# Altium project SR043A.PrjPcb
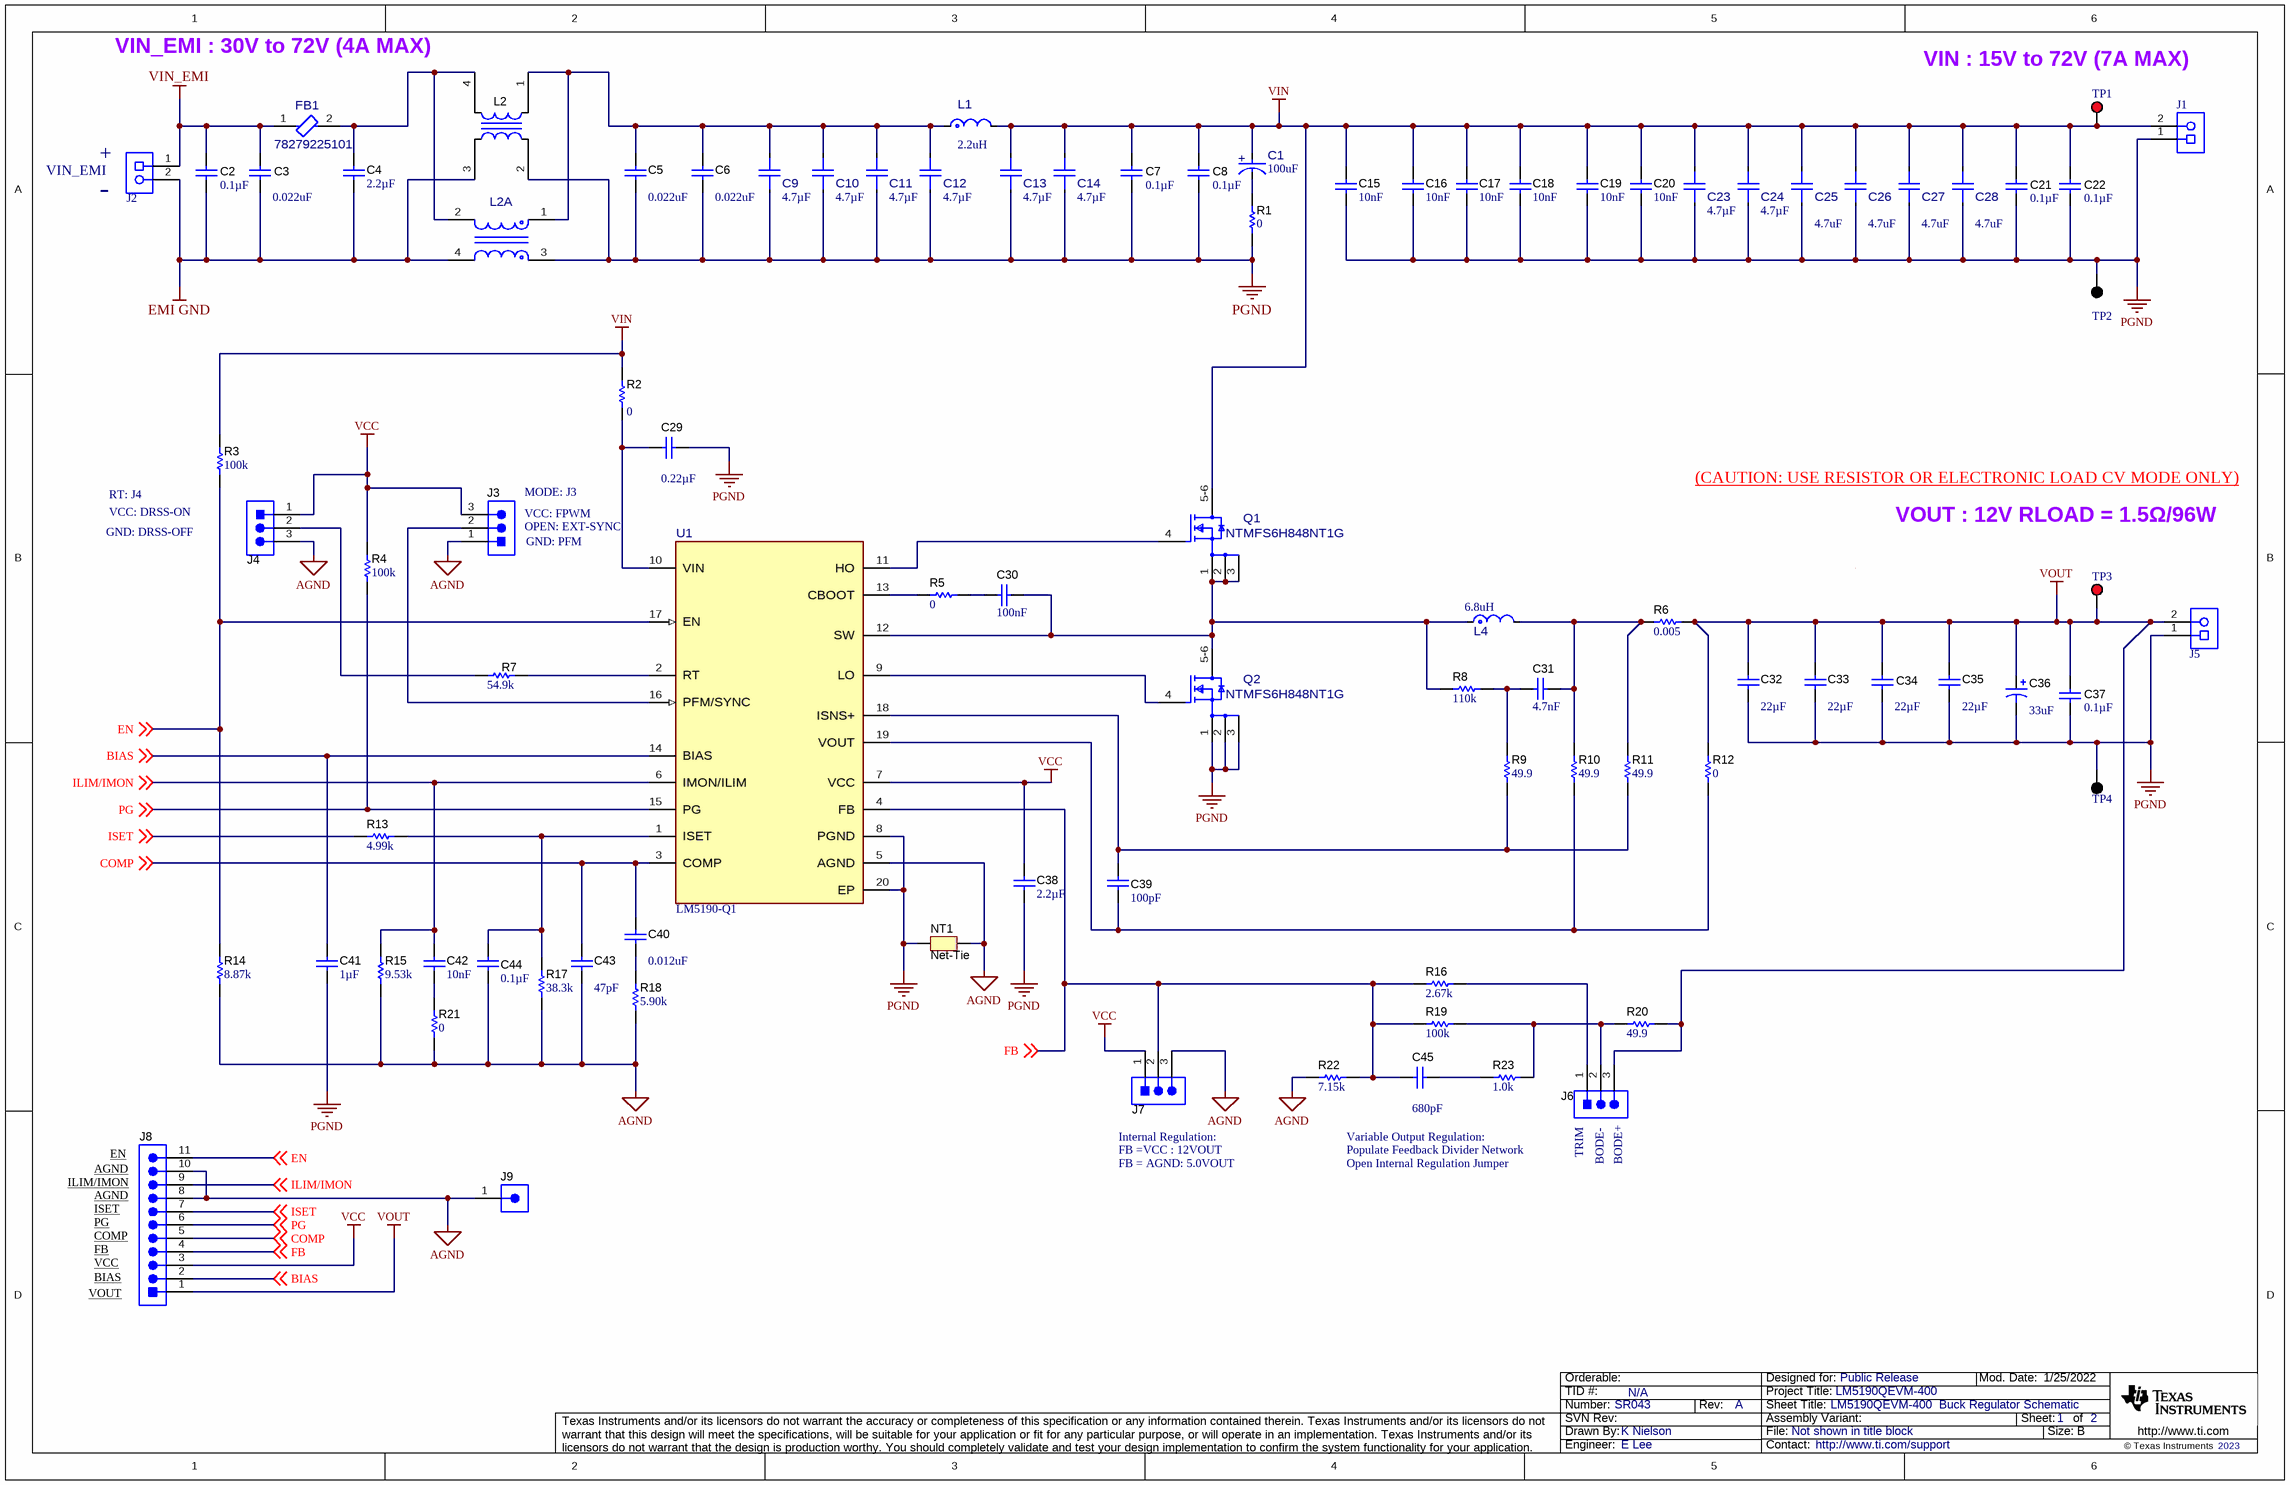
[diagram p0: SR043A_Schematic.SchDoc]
CopyrightYear: 2023; PCB_Layout: K Nielson; PCB_Rev: A; PRJ_Customer: Public Release; PRJ_Engineer: E Lee; PRJ_Number: SR043; PRJ_Title: LM5190QEVM-400; SCH_Rev: A; TechSupport: http://www.ti.com/support; TID: N/A
2 sheets, 121 parts. Net scope: global (net labels, ports and power ports of the same name join across sheets).
Board file: SR043A.PcbDoc
Sheets:
  SR043A_Schematic.SchDoc
  SR043A_Hardware.SchDoc

## Sheet SR043A_Schematic.SchDoc: LM5190QEVM-400  Buck Regulator Schematic
size 431 x 279 mm; Date: Not shown in title block; ApprovedBy: Not shown in title block; CheckedBy: Not shown in title block; Author: Not shown in title block; CompanyName: Not shown in title block; DrawnBy: K Nielson; Engineer: Not shown in title block; Organization: Not shown in title block; Address1: Not shown in title block; Address2: Not shown in title block; Address3: Not shown in title block; Address4: Not shown in title block; DocumentNumber: 1; Revision: Use project parameter SCH_Rev; SheetNumber: 1; SheetTotal: 2; PageSetup: Record=PageOptions¦CenterHorizontal=True¦CenterVertical=True¦PrintScale=1.00¦XCorrection=1.00¦YCorrection=1.00¦PrintKind=0¦BorderSize=5000000¦LeftOffset=0¦BottomOffset=0¦Orientation=2¦PaperLength=1000¦PaperWidth=1000¦Scale=100¦PaperSource=15¦PrintQuality=600¦MediaType=1¦DitherType=10¦PaperKind=Letter¦PrintScaleMode=1

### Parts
C1  ValueDisplayed: 100uF  [FP-EMVY101ARA101MKE0S_RADIAL-MFG]  (hidden comment: EMVY101ARA101MKE0S)
C2  ValueDisplayed: 0.1µF  [0603L]  (hidden comment: HMK107B7104MAHT)
C3  ValueDisplayed: 0.022uF  [0603L]  (hidden comment: CGA3E2X7R2A223K080AA)
C4  Cap_F: 2.2µF  [1206_190]  (hidden comment: CGA5L3X7S2A225M160AB)
C5  ValueDisplayed: 0.022uF  [0603L]  (hidden comment: CGA3E2X7R2A223K080AA)
C6  ValueDisplayed: 0.022uF  [0603L]  (hidden comment: CGA3E2X7R2A223K080AA)
C7  ValueDisplayed: 0.1µF  [0603L]  (hidden comment: HMK107B7104MAHT)
C8  ValueDisplayed: 0.1µF  [0603L]  (hidden comment: HMK107B7104MAHT)
C9  Cap_F: 4.7µF  [FP-CNC6P1X7R2A475K250AE_1210-MFG]  (hidden comment: CNC6P1X7R2A475K250AE)
C10  Cap_F: 4.7µF  [FP-CNC6P1X7R2A475K250AE_1210-MFG]  (hidden comment: CNC6P1X7R2A475K250AE)
C11  Cap_F: 4.7µF  [FP-CNC6P1X7R2A475K250AE_1210-MFG]  (hidden comment: CNC6P1X7R2A475K250AE)
C12  Cap_F: 4.7µF  [FP-CNC6P1X7R2A475K250AE_1210-MFG]  (hidden comment: CNC6P1X7R2A475K250AE)
C13  Cap_F: 4.7µF  [FP-CNC6P1X7R2A475K250AE_1210-MFG]  (hidden comment: CNC6P1X7R2A475K250AE)
C14  Cap_F: 4.7µF  [FP-CNC6P1X7R2A475K250AE_1210-MFG]  (hidden comment: CNC6P1X7R2A475K250AE)
C15  Cap_F: 10nF  [0603L]  (hidden comment: 885012206114)
C16  Cap_F: 10nF  [0603L]  (hidden comment: 885012206114)
C17  Cap_F: 10nF  [0603L]  (hidden comment: 885012206114)
C18  Cap_F: 10nF  [0603L]  (hidden comment: 885012206114)
C19  Cap_F: 10nF  [0603L]  (hidden comment: 885012206114)
C20  Cap_F: 10nF  [0603L]  (hidden comment: 885012206114)
C21  ValueDisplayed: 0.1µF  [0603L]  (hidden comment: HMK107B7104MAHT)
C22  ValueDisplayed: 0.1µF  [0603L]  (hidden comment: HMK107B7104MAHT)
C23  Cap_F: 4.7µF  [FP-CNC6P1X7R2A475K250AE_1210-MFG]  (hidden comment: CNC6P1X7R2A475K250AE)
C24  Cap_F: 4.7µF  [FP-CNC6P1X7R2A475K250AE_1210-MFG]  (hidden comment: CNC6P1X7R2A475K250AE)
C25  ValueDisplayed: 4.7uF  [FP-CNC6P1X7R2A475K250AE_1210-MFG]  (hidden comment: CNC6P1X7R2A475K250AE)
C26  ValueDisplayed: 4.7uF  [FP-CNC6P1X7R2A475K250AE_1210-MFG]  (hidden comment: CNC6P1X7R2A475K250AE)
C27  ValueDisplayed: 4.7uF  [FP-CNC6P1X7R2A475K250AE_1210-MFG]  (hidden comment: CNC6P1X7R2A475K250AE)
C28  ValueDisplayed: 4.7uF  [FP-CNC6P1X7R2A475K250AE_1210-MFG]  (hidden comment: CNC6P1X7R2A475K250AE)
C29  ValueDisplayed: 0.22µF  [0603L]  (hidden comment: HMK107C7224MAHTE)
C30  Cap_F: 100nF  [0603L]  (hidden comment: HMK107B7104MAHT)
C31  Cap_F: 4.7nF  [0603L]  (hidden comment: GCM188R72A472KA37D)
C32  ValueDisplayed: 22µF  [1210_280]  (hidden comment: C1210C226K3RAC7800)
C33  ValueDisplayed: 22µF  [1210_280]  (hidden comment: C1210C226K3RAC7800)
C34  ValueDisplayed: 22µF  [1210_280]  (hidden comment: C1210C226K3RAC7800)
C35  ValueDisplayed: 22µF  [1210_280]  (hidden comment: C1210C226K3RAC7800)
C36  ValueDisplayed: 33uF  [CAPSMT_62_F60]  (hidden comment: EMVH250ADA330MF60G)
C37  ValueDisplayed: 0.1µF  [0603L]  (hidden comment: HMK107B7104MAHT)
C38  Cap_F: 2.2µF  [0603L]  (hidden comment: CGA3E1X7S1C225M080AC)
C39  ValueDisplayed: 100pF  [0603L]  (hidden comment: GRM1885C2A101JA01D)
C40  ValueDisplayed: 0.012uF  [0603L]  (hidden comment: C0603C123J3GACTU)
C41  Cap_F: 1µF  [0603L]  (hidden comment: 06033C105KAT2A)
C42  Cap_F: 10nF  [0603L]  (hidden comment: 885012206114)
C43  ValueDisplayed: 47pF  [0603L]  (hidden comment: CGA3E2NP01H470J080AA)
C44  ValueDisplayed: 0.1µF  [0603L]  (hidden comment: HMK107B7104MAHT)
C45  ValueDisplayed: 680pF  [0603L]  (hidden comment: GRM1885C1E681JA01D)
FB1  78279225101  [FP-78279225101_3312-MFG]
J1  691253510002  [FP-691253510002_CONN_TERM_BLOCK2-MFG]  (value not drawn)
J2  691253510002  [FP-691253510002_CONN_TERM_BLOCK2-MFG]  (value not drawn)
J3  61300311121  [WURTH_61300311121]  (value not drawn)
J4  61300311121  [WURTH_61300311121]  (value not drawn)
J5  691253510002  [FP-691253510002_CONN_TERM_BLOCK2-MFG]  (value not drawn)
J6  61300311121  [WURTH_61300311121]  (value not drawn)
J7  61300311121  [WURTH_61300311121]  (value not drawn)
J8  TSW-111-07-G-S  [TSW-111-07-G-S]  (value not drawn)
J9  1040  [CONN_1040]  (value not drawn)
L1  value 2.2uH  [FP-XGL4040-222MEC_SMT2_4MM0_4MM0-MFG]  (hidden comment: XGL4040-222MEC)
L2  ACM70V-701-2PL-TL00  [IND_TDK_ACM7060]  (value not drawn)
L2A  744237701  [FP-744237701_SMT_CHOKE_12MM00_11MM00-MFG]  (value not drawn)
L4  value 6.8uH  [FP-XGL1060-682MEC_SMT_IND_10MM0_11MM3-MFG]  (hidden comment: XGL1060-682MEC)
NT1  Net-Tie  [Net-Tie_10mil]  (net tie, no BOM)
Q1  NTMFS6H848NT1G  [FP-NTMFS6H848NT1G_DFN5-MFG]
Q2  NTMFS6H848NT1G  [FP-NTMFS6H848NT1G_DFN5-MFG]
R1  ValueDisplayed: 0  [1206]  (hidden comment: RCA12060000ZSEA)
R2  ValueDisplayed: 0  [0603L]  (hidden comment: RC0603JR-070RL)
R3  ValueDisplayed: 100k  [0603L]  (hidden comment: RC0603FR-07100KL)
R4  ValueDisplayed: 100k  [0603L]  (hidden comment: RC0603FR-07100KL)
R5  ValueDisplayed: 0  [0603L]  (hidden comment: RC0603JR-070RL)
R6  ValueDisplayed: 0.005  [2512_WIDE]  (hidden comment: FCSL64R005FER)
R7  ValueDisplayed: 54.9k  [0603L]  (hidden comment: RC0603FR-0754K9L)
R8  ValueDisplayed: 110k  [0603L]  (hidden comment: CRCW0603110KFKEA)
R9  ValueDisplayed: 49.9  [0603L]  (hidden comment: ERJ-3EKF49R9V)
R10  ValueDisplayed: 49.9  [0603L]  (hidden comment: ERJ-3EKF49R9V)
R11  ValueDisplayed: 49.9  [0603L]  (hidden comment: ERJ-3EKF49R9V)
R12  ValueDisplayed: 0  [0603L]  (hidden comment: RC0603JR-070RL)
R13  ValueDisplayed: 4.99k  [0603L]  (hidden comment: RC0603FR-074K99L)
R14  ValueDisplayed: 8.87k  [0603L]  (hidden comment: RC0603FR-078K87L)
R15  ValueDisplayed: 9.53k  [0603L]  (hidden comment: RC0603FR-079K53L)
R16  ValueDisplayed: 2.67k  [0603L]  (hidden comment: RC0603FR-072K67L)
R17  ValueDisplayed: 38.3k  [0603L]  (hidden comment: RC0603FR-0738K3L)
R18  ValueDisplayed: 5.90k  [0603L]  (hidden comment: RC0603FR-075K9L)
R19  ValueDisplayed: 100k  [0603L]  (hidden comment: RC0603FR-07100KL)
R20  ValueDisplayed: 49.9  [0603L]  (hidden comment: M55342K12B49D9T)
R21  ValueDisplayed: 0  [0603L]  (hidden comment: RC0603JR-070RL)
R22  ValueDisplayed: 7.15k  [0603L]  (hidden comment: RC0603FR-077K15L)
R23  ValueDisplayed: 1.0k  [0603L]  (hidden comment: RC0603JR-071KL)
TP1  5000  [Keystone5000]  (value not drawn)
TP2  5001  [Keystone5001]  (value not drawn)
TP3  5000  [Keystone5000]  (value not drawn)
TP4  5001  [Keystone5001]  (value not drawn)
U1  LM5190-Q1  [RGY0019B-MFG]

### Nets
AGND: C43.2 C44.1 J3.1 J4.3 J7.3 J8.8 J8.10 J9.1 NT1.2 R14.1 R15.1 R17.1 R18.1 R21.2 R22.1 U1.5(AGND)
EMI GND: C2.2 C3.2 C4.2 J2.2 L2.3 L2A.4
PGND: C5.2 C6.2 C7.2 C8.2 C9.1 C10.1 C11.1 C12.1 C13.1 C14.1 C15.2 C16.2 C17.2 C18.2 C19.2 C20.2 C21.2 C22.2 C23.1 C24.1 C25.1 C26.1 C27.1 C28.1 C29.1 C32.2 C33.2 C34.2 C35.2 C36.2(-) C37.2 C38.2 C41.2 J1.1 J5.1 L2.2 L2A.3 NT1.1 Q2.1(S) Q2.2(S) Q2.3(S) R1.2 TP2.1 TP4.1 U1.8(PGND) U1.20(EP)
VCC: C38.1 J3.3 J4.1 J7.1 J8.3 R4.2 U1.7(VCC)
VIN: C1.2(ANODE) C7.1 C8.1 C13.2 C14.2 C15.1 C16.1 C17.1 C18.1 C19.1 C20.1 C21.1 C22.1 C23.2 C24.2 C25.2 C26.2 C27.2 C28.2 J1.2 L1.2 Q1.5-6(D) R2.2 R3.2 TP1.1
VIN_EMI: C2.1 C3.1 FB1.1 J2.1
VOUT: C32.1 C33.1 C34.1 C35.1 C36.1(+) C37.1 J5.2 J6.3 J8.1 R6.2 R12.2 R20.2 TP3.1
BIAS: C41.1 J8.2 U1.14(BIAS) ; off-sheet BIAS
COMP: C40.1 C43.1 J8.5 U1.3(COMP) ; off-sheet COMP
EN: J8.11 R3.1 R14.2 U1.17(EN) ; off-sheet EN
FB: C45.2 J7.2 J8.4 R16.1 R19.1 R22.2 U1.4(FB) ; off-sheet FB
ILIM/IMON: C42.1 J8.9 R15.2 U1.6(IMON/ILIM) ; off-sheet ILIM/IMON
ISET: J8.7 R13.1 ; off-sheet ISET
PG: J8.6 R4.1 U1.15(PG) ; off-sheet PG
NetC1_1: C1.1(CATHODE) R1.1
NetC4_1: C4.1 FB1.2 L2.4 L2A.2
NetC5_1: C5.1 C6.1 C9.2 C10.2 C11.2 C12.2 L1.1 L2.1 L2A.1
NetC29_2: C29.2 R2.1 U1.10(VIN)
NetC30_1: C30.1 L4.1 Q1.1(S) Q1.2(S) Q1.3(S) Q2.5-6(D) R8.1 U1.12(SW)
NetC30_2: C30.2 R5.2
NetC31_1: C31.1 R8.2 R9.2
NetC31_2: C31.2 L4.2 R6.1 R10.2 R11.1
NetC39_1: C39.1 R10.1 R12.1 U1.19(VOUT)
NetC39_2: C39.2 R9.1 R11.2 U1.18(ISNS+)
NetC40_2: C40.2 R18.2
NetC42_2: C42.2 R21.1
NetC44_2: C44.2 R13.2 R17.2 U1.1(ISET)
NetC45_1: C45.1 R23.1
NetJ3_2: J3.2 U1.16(PFM/SYNC)
NetJ4_2: J4.2 R7.2
NetJ6_1: J6.1 R16.2
NetJ6_2: J6.2 R19.2 R20.1 R23.2
NetQ1_4: Q1.4(G) U1.11(HO)
NetQ2_4: Q2.4(G) U1.9(LO)
NetR5_1: R5.1 U1.13(CBOOT)
NetR7_1: R7.1 U1.2(RT)

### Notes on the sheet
- VIN_EMI : 30V to 72V (4A MAX)
- VIN : 15V to 72V (7A MAX)
- (near J2) +
- VIN_EMI
- (near J2) -
- RT: J4
- (near J3) MODE: J3
- (CAUTION: USE RESISTOR OR ELECTRONIC LOAD CV MODE ONLY) <aDD tEST pOINT>
- GND: DRSS-OFF
- (near R3) VCC: DRSS-ON
- (near J3) VCC: FPWM
- (near J3) OPEN: EXT-SYNC
- (near J3) GND: PFM
- VOUT : 12V RLOAD = 1.5Ω/96W
- (near J8) AGND <aDD tEST pOINT>
- (near J8) EN <aDD tEST pOINT>
- Internal Regulation:
- FB =VCC : 12VOUT
- FB = AGND: 5.0VOUT
- Variable Output Regulation:
- Populate Feedback Divider Network
- Open Internal Regulation Jumper
- (near J6) TRIM
- (near J6) BODE-
- (near J6) BODE+
- (near J8) ILIM/IMON <aDD tEST pOINT>
- (near J8) ISET <aDD tEST pOINT>
- PG <aDD tEST pOINT>
- (near J8) COMP <aDD tEST pOINT>
- VOUT <aDD tEST pOINT>
- (near J8) BIAS <aDD tEST pOINT>
- FB <aDD tEST pOINT>
- VCC <aDD tEST pOINT>

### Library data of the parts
C1 = CMP-0094051-1: 100uF 100V 20% Aluminum Electrolytic Capacitors Radial, Can - SMD - 5000 Hrs @ 105°C; Manufacturer: United Chemi-Con; Value: 100µF; IRMS_A: 450mA; Life: 5000Hours; SizeZ_mm: 14mm; AEC Grade: Grade 2; Leakage Current: 100uA; Dissipation Factor: 10%; AEC Qualified: Yes
C2 C7 C8 C21 C22 C37 = CMP-0078500-1: CAP, CERM, 0.1 µF,  VAC/100 VDC,+/- 20%, X7R, AEC-Q200 Grade 1, 0603; Manufacturer: Taiyo Yuden; TaMin_C: -55°C; Polarized: N; SizeAreaWB_mm2: 4.68; U/M: EA; Value: 0.1uF; TaMax_C: 125°C; SizeZ_mm: 1; SizeX_mm: 1.6; SizeY_mm: 0.8; Cap_Case: 0603; Value2: 100V; SizeArea_mm2: 1.28; AEC Qualified: Y; Cap_F: 100nF; AEC Category: Q200
C3 C5 C6 = CMP-0007086-4: CAP, CERM, 0.022 uF, 100 V, +/- 10%, X7R, AEC-Q200 Grade 1, 0603; Manufacturer: TDK; TaMin_C: -55°C; ESR_ohm: 83.542m; Polarized: N; SizeAreaWB_mm2: 4.68; Value1: 0.083542 ohm; U/M: EA; TaMax_C: 125°C; SizeZ_mm: 1; SizeX_mm: 1.6; SizeY_mm: 0.8; Cap_Case: 0603; Value2: 100V; SizeArea_mm2: 1.28; AEC Qualified: Y; Cap_F: 22nF; IRMS_A: 609.312mA; AEC Category: Q200
C4 = CMP-0008791-2: CAP, CERM, 2.2 uF, 100 V, +/- 20%, X7S, AEC-Q200 Grade 1, 1206_190; Manufacturer: TDK; TaMin_C: -55°C; Polarized: N; SizeAreaWB_mm2: 10.92; Value1: Unknown; U/M: EA; Value: 2.2uF; TaMax_C: 125°C; SizeZ_mm: 1.9; SizeX_mm: 3.2; SizeY_mm: 1.6; Cap_Case: 1206; Value2: 100V; SizeArea_mm2: 5.12; AEC Qualified: Y; AEC Grade: 1; AEC Category: Q200
C9-C14 C23 C24 = CMP-0094503-1: 4.7 µF ±10% 100V Ceramic Capacitor X7R 1210 (3225 Metric); Manufacturer: TDK; TempCo: 15%; Value: 4.7µF; SizeZ_mm: 2.8mm; AEC Qualified: No; ValueDisplayed: 4.7uF
C15-C20 C42 = CMP-0079993-1: CAP, CERM, 0.01 µF, 100 V,+/- 10%, X7R, 0603; Manufacturer: Wurth Elektronik; TaMin_C: -55°C; Polarized: N; SizeAreaWB_mm2: 4.68; U/M: EA; Value: 0.01uF; TaMax_C: 105°C; SizeZ_mm: 1; SizeX_mm: 1.6; SizeY_mm: 0.8; Cap_Case: 0603; Value2: 100V; SizeArea_mm2: 1.28; AEC Category: Q200; ValueDisplayed: 0.01µF
C25-C28 = CMP-0094503-1: 4.7 µF ±10% 100V Ceramic Capacitor X7R 1210 (3225 Metric); Manufacturer: TDK; TempCo: 15%; Value: 4.7µF; SizeZ_mm: 2.8mm; AEC Qualified: No
C29 = CMP-0077895-3: CAP, CERM, 0.22 µF, 100 V,+/- 20%, X7S, AEC-Q200 Grade 1, 0603; Manufacturer: Taiyo Yuden; TaMin_C: -55°C; Polarized: N; SizeAreaWB_mm2: 4.68; U/M: EA; Value: 0.22uF; TaMax_C: 125°C; SizeZ_mm: 1.0; SizeX_mm: 1.6; SizeY_mm: 0.8; Cap_Case: 0603; Value2: 100V; SizeArea_mm2: 1.28; AEC Qualified: Y; Cap_F: 220nF; AEC Grade: 1; AEC Category: Q200
C30 = CMP-0078500-1: CAP, CERM, 0.1 µF,  VAC/100 VDC,+/- 20%, X7R, AEC-Q200 Grade 1, 0603; Manufacturer: Taiyo Yuden; TaMin_C: -55°C; Polarized: N; SizeAreaWB_mm2: 4.68; U/M: EA; Value: 0.1uF; TaMax_C: 125°C; SizeZ_mm: 1; SizeX_mm: 1.6; SizeY_mm: 0.8; Cap_Case: 0603; Value2: 100V; SizeArea_mm2: 1.28; AEC Qualified: Y; AEC Category: Q200; ValueDisplayed: 0.1µF
C31 = CMP-0079247-1: CAP, CERM, 4700 pF, 100 V,+/- 10%, X7R, AEC-Q200 Grade 1, 0603; Manufacturer: MuRata; TaMin_C: -55°C; Polarized: N; SizeAreaWB_mm2: 4.68; U/M: EA; Value: 4700pF; TaMax_C: 125°C; SizeZ_mm: 1; SizeX_mm: 1.6; SizeY_mm: 0.8; Cap_Case: 0603; Value2: 100V; SizeArea_mm2: 1.28; AEC Qualified: Y; AEC Category: Q200
C32-C35 = CMP-0082266-1: CAP, CERM, 22 µF, 25 V,+/- 10%, X7R, 1210; Manufacturer: Kemet; TaMin_C: -55°C; Polarized: N; SizeAreaWB_mm2: 14.7; Value1: 0.001 ohm; U/M: EA; Value: 22uF; TaMax_C: 125°C; SizeZ_mm: 2.8; SizeX_mm: 3.2; SizeY_mm: 2.5; Cap_Case: 1210; Value2: 25V; SizeArea_mm2: 8; AEC Category: Q200; ESR_ohm: 1m; Green_Lifecycle: Active; Green_REACh: Incomplete
C36 = CMP-0010917-1: CAP, AL, 33 uF, 25 V, +/- 20%, 1.6 ohm, SMD; Manufacturer: Chemi-Con; TaMin_C: -40°C; ESR_ohm: 1.6; Polarized: Y; SizeAreaWB_mm2: 77.44; Value1: 1.6 ohm; U/M: EA; Value: 33uF; TaMax_C: 125°C; SizeZ_mm: 6; SizeX_mm: 6.8; Cap_Case: F60; Value2: 25V; SizeArea_mm2: 46.24; CompType: Capacitor; Cap_F: 33µF; IRMS_A: 69mA; AEC Category: Q200
C38 = CMP-0007068-4: CAP, CERM, 2.2 uF, 16 V, +/- 20%, X7S, AEC-Q200 Grade 1, 0603; Manufacturer: TDK; TaMin_C: -55°C; Polarized: N; SizeAreaWB_mm2: 4.68; Value1: Unknown; U/M: EA; Value: 2.2uF; TaMax_C: 125°C; SizeZ_mm: 1; SizeX_mm: 1.6; SizeY_mm: 0.8; Cap_Case: 0603; Value2: 16V; SizeArea_mm2: 1.28; AEC Qualified: Y; AEC Category: Q200
C39 = CMP-0007237-4: CAP, CERM, 100 pF, 100 V, +/- 5%, C0G/NP0, 0603; Manufacturer: MuRata; SizeZ_mm: 1; VDC_V: 100V; Value: 100pF; TaMin_C: -55°C; Polarized: N; SizeAreaWB_mm2: 4.68; Value1: Unknown; U/M: EA; TaMax_C: 125°C; SizeX_mm: 1.6; SizeY_mm: 0.8; Cap_Case: 0603; SizeArea_mm2: 1.28; AEC Category: Q200
C40 = CMP-0006876-4: CAP, CERM, 0.012 uF, 25 V, +/- 5%, C0G/NP0, 0603; Manufacturer: Kemet; TaMin_C: -55°C; Polarized: N; SizeAreaWB_mm2: 4.68; U/M: EA; TaMax_C: 125°C; SizeZ_mm: 1; SizeX_mm: 1.6; SizeY_mm: 0.8; Cap_Case: 0603; Value2: 25V; SizeArea_mm2: 1.28; Cap_F: 12nF; AEC Category: Q200; Value1: Unknown
C41 = CMP-0006754-4: CAP, CERM, 1 uF, 25 V, +/- 10%, X7R, 0603; Manufacturer: AVX; TaMin_C: -55°C; Polarized: N; SizeAreaWB_mm2: 4.68; Value1: Unknown; U/M: EA; Value: 1uF; TaMax_C: 125°C; SizeZ_mm: 1; SizeX_mm: 1.6; SizeY_mm: 0.8; Cap_Case: 0603; Value2: 25V; SizeArea_mm2: 1.28; AEC Category: Q200
C43 = CMP-0080062-1: CAP, CERM, 47 pF, 50 V,+/- 5%, C0G/NP0, AEC-Q200 Grade 0, 0603; Manufacturer: TDK; TaMin_C: -55°C; Polarized: N; SizeAreaWB_mm2: 4.68; U/M: EA; Value: 47pF; TaMax_C: 150°C; SizeZ_mm: 1; SizeX_mm: 1.6; SizeY_mm: 0.8; Cap_Case: 0603; Value2: 50V; SizeArea_mm2: 1.28; AEC Qualified: Y; AEC Category: Q200; AEC Grade: 0
C44 = CMP-0078500-1: CAP, CERM, 0.1 µF,  VAC/100 VDC,+/- 20%, X7R, AEC-Q200 Grade 1, 0603; Manufacturer: Taiyo Yuden; AEC Grade: 1; AEC Qualified: Y; Cap_F: 100nF; VDC_V: 100V; Value: 0.1uF; TaMin_C: -55°C; Polarized: N; SizeAreaWB_mm2: 4.68; U/M: EA; TaMax_C: 125°C; SizeX_mm: 1.6; SizeY_mm: 0.8; Cap_Case: 0603; SizeArea_mm2: 1.28; AEC Category: Q200
C45 = CMP-0007166-4: CAP, CERM, 680 pF, 25 V, +/- 5%, C0G/NP0, 0603; Manufacturer: MuRata; TaMin_C: -55°C; Polarized: N; SizeAreaWB_mm2: 4.68; Value1: Unknown; U/M: EA; Value: 680pF; TaMax_C: 125°C; SizeZ_mm: 1; SizeX_mm: 1.6; SizeY_mm: 0.8; Cap_Case: 0603; Value2: 25V; SizeArea_mm2: 1.28; AEC Category: Q200
FB1 = CMP-0097847-1: 100 Ohms @ 100 MHz 1 Power Line Ferrite Bead 3312 (8531 Metric) 10A 4mOhm; Manufacturer: Wurth Electronics; AEC Grade: Grade 1; Impedance At Frequency: 100Ω @ 100MHz; SizeZ_mm: 2.48mm; TaMax_C: +85°C; Tolerance_%: 25%; DCR_ohm: 4m; TaMin_C: -55°C; AEC Qualified: Yes
J1 J5 = CMP-0095936-2: Manufacturer: Wurth Electronics; Current_A: 16A; Max Wire Gauge: 12; Min Wire Gauge: 30; SizeZ_mm: 18.1mm; AEC Qualified: No; Is Female: yes; ContactFinish: Tin,Nickel; Voltage_V: 300V; DUT-Pitch_mm: 5.08mm; Conn Orientation: Horizontal; Conn Gender: Female; Row_Count: 1
J2 = CMP-0095936-2: 2 Position Wire to Board Terminal Block Horizontal with Board 0.200" (5.08mm) Through Hole; Manufacturer: Wurth Electronics; ContactFinish: Tin,Nickel; Current_A: 16A; Row_Count: 1; Voltage_V: 300V; Max Wire Gauge: 12; Min Wire Gauge: 30; SizeZ_mm: 18.1mm; AEC Qualified: No; Is Female: yes; Conn Gender: Female
J3 J4 J6 J7 = CMP-0054796-4: Header, 2.54 mm, 3x1, Gold, TH; Manufacturer: Wurth Elektronik; Green_REACh: Passed; Green_Lifecycle: Active; CT: FALSE; CNHeader: TRUE
J8 = CMP-0075454-1: Header, 100mil, 11x1, Gold, TH; Manufacturer: Samtec; Pitch_mm: 2.54; Cert_VDE: N; Gender: Male; Cert_CSA: Y; Voltage_V: 550V; Green_REACh: Passed; Current_A: 6.3A; CT: False; Green_Lifecycle: Active; Row_Count: 1; CNHeader: True
J9 = CMP-0055161-1: Manufacturer: Keystone; CNHeader: FALSE; Green_Lifecycle: Active; Green_REACh: Passed; CompType: Test Point; CT: TRUE
L1 = CMP-0120523-1: 2.2 µH Shielded Molded Inductor 11 A 11.5mOhm Max 1616 (4040 Metric); Manufacturer: Coilcraft; AEC Grade: Grade 1; AEC Qualified: Yes; DCR_ohm: 11.5m; Ind_H: 2.2µH; Irms: 11A; Isat: 3.1A; Material: Composite; SizeZ_mm: 4.1mm; Self Resonant Frequency: 37MHz; Shrouded: true; TaMax_C: +125°C; TaMin_C: -40°C; Test Frequency: 1MHz; Tolerance_%: 20%
L2 = CMP-0085405-1: Coupled inductor, 0.015 ohm, AEC-Q200 Grade 1, SMD; Manufacturer: TDK; DCR_ohm: 0.015; AEC Qualified: Y; AEC Category: Q200; AEC Grade: 1
L2A = CMP-0094052-1: 9 µH @ 100 kHz 2 Line Common Mode Choke Surface Mount 700 Ohms @ 100 MHz 8A DCR 6mOhm; Manufacturer: Wurth Electronics; SizeZ_mm: 6mm; Impedance At Frequency: 700Ω @ 100MHz; Ind_H: 9µH; AEC Grade: Grade 1; Tolerance_%: 50%; TaMax_C: +80°C; DCR_ohm: 6m; Test Frequency: 100kHz; TaMin_C: -40°C; AEC Qualified: Yes
L4 = CMP-0120488-1: 6.8 µH Shielded Molded Inductor 14.8 A 12.5mOhm Max Nonstandard; Manufacturer: Coilcraft; AEC Grade: Grade 1; AEC Qualified: Yes; DCR_ohm: 12.5m; Ind_H: 6.8µH; Irms: 14.8A; Isat: 7.3A; Material: Composite; SizeZ_mm: 6mm; Self Resonant Frequency: 14MHz; Shrouded: true; TaMax_C: +125°C; TaMin_C: -40°C; Test Frequency: 1MHz; Tolerance_%: 20%
NT1 = CMP-0078142-6: Single point connection between nets.
Q1 = CMP-0121870-1: N-Channel 80 V 13A (Ta), 57A (Tc) 3.7W (Ta), 73W (Tc) Surface Mount 5-DFN (5x6) (8-SOFL); Manufacturer: onsemi; Transconductance: 52S; QgTyp_nC: 16nC @ 10V; Typ Forward Diode Voltage: 0.8V; Turn On Delay Time: 13ns; VdsMax_V: 1.2V; Rdson45_ohm: 8.1m; Number Of N Channels: 1; Reverse Recovery Time: 39ns; TJmax_C: +175°C; ChMode: False; Threshold Vgs Min: 2V; Pulse Drain Current: 308A; Rthja Max: 41°C/W; Input Capacitace At Vds: 1180pF @ 40V; Turn Off Delay Time: 34ns; Reverse Recovery Charge: 41nC; Standoff Height: 0mm; AEC Qualified: No; SizeZ_mm: 1.1mm; Vgs_V: 20V; Threshold Vgs Max: 4V; Drain To Source Breakdown Voltage: 80V
Q2 = CMP-0121870-1: N-Channel 80 V 13A (Ta), 57A (Tc) 3.7W (Ta), 73W (Tc) Surface Mount 5-DFN (5x6) (8-SOFL); Manufacturer: onsemi; Transconductance: 52S; QgTyp_nC: 16nC @ 10V; Typ Forward Diode Voltage: 0.8V; Turn On Delay Time: 13ns; VdsMax_V: 1.2V; Rdson45_ohm: 8.1m; Number Of N Channels: 1; Reverse Recovery Time: 39ns; TJmax_C: +175°C; ChMode: False; Threshold Vgs Min: 2V; Pulse Drain Current: 308A; Rthja Max: 41°C/W; Input Capacitace At Vds: 1180pF @ 40V; Turn Off Delay Time: 34ns; Reverse Recovery Charge: 41nC; AEC Qualified: No; SizeZ_mm: 1.1mm; Vgs_V: 20V; Threshold Vgs Max: 4V; Drain To Source Breakdown Voltage: 80V; Standoff Height: 0mm
R1 = CMP-0018760-2: RES, 0, 5%, 0.25 W, AEC-Q200 Grade 0, 1206; Manufacturer: Vishay-Dale; Power_W: 250mW; TempCo: ppm/C; Value_Code: 0000; U/M: EA; Value: 0; EIA_Code: E24; SizeX_mm: 3.2; SizeY_mm: 1.6; SizeZ_mm: 1.35; Value2: 0.25W; SizeArea_mm2: 5.12; AEC Qualified: Y; AEC Category: Q200
R2 R12 R21 = CMP-0025885-5: RES, 0, 5%, 0.1 W, 0603; Manufacturer: Yageo; Power_W: 100mW; TempCo: 200 ppm/C; SizeZ_mm: 1; AEC Qualified: N; VDC_V: 75V; Value_Code: 0000; Value: 0; EIA_Code: E24; SizeX_mm: 1.6; Value2: 0.1W; SizeArea_mm2: 1.28; AEC Category: Q200; SizeY_mm: 0.8; SizeAreaWB_mm2: 4.68
R3 R19 = CMP-0022735-5: RES, 100 k, 1%, 0.1 W, 0603; Manufacturer: Yageo; Power_W: 100mW; TempCo: 100 ppm/C; Value: 100k; EIA_Code: E96; SizeX_mm: 1.6; SizeY_mm: 0.8; SizeZ_mm: 1; Value2: 0.1W; SizeArea_mm2: 1.28; AEC Qualified: N; VDC_V: 75V; AEC Category: Q200; SizeAreaWB_mm2: 4.68
R4 = CMP-0022735-5: RES, 100 k, 1%, 0.1 W, 0603; Manufacturer: Yageo; Power_W: 100mW; TempCo: 100 ppm/C; Value: 100k; SizeX_mm: 1.6; SizeY_mm: 0.8; SizeZ_mm: 1; Value2: 0.1W; SizeArea_mm2: 1.28; AEC Qualified: N; VDC_V: 75V; AEC Category: Q200; EIA_Code: E96; SizeAreaWB_mm2: 4.68
R5 = CMP-0025885-5: RES, 0, 5%, 0.1 W, 0603; Manufacturer: Yageo; Power_W: 100mW; TempCo: 200 ppm/C; Value_Code: 0000; Value: 0; EIA_Code: E24; SizeX_mm: 1.6; SizeZ_mm: 1; Value2: 0.1W; SizeArea_mm2: 1.28; AEC Qualified: N; VDC_V: 75V; AEC Category: Q200; SizeY_mm: 0.8; SizeAreaWB_mm2: 4.68
R6 = CMP-0015079-2: RES, 0.005, 1%, 2 W, 2512 WIDE; Manufacturer: Ohmite; Power_W: 2W; TempCo: 75 ppm/C; SizeAreaWB_mm2: 43.16; Value_Code: 5L000; U/M: EA; Value: 0.005; EIA_Code: E96; Res_ohm: 5m; SizeX_mm: 3.2; SizeY_mm: 6.3; SizeZ_mm: 0.7; SizeArea_mm2: 20.16; AEC Category: Q200
R7 = CMP-0023180-5: RES, 54.9 k, 1%, 0.1 W, 0603; Manufacturer: Yageo; Power_W: 100mW; TempCo: 100 ppm/C; Value_Code: 54k9; Value: 54.9k; EIA_Code: E96; SizeX_mm: 1.6; SizeY_mm: 0.8; SizeZ_mm: 1; Value2: 0.1W; SizeArea_mm2: 1.28; AEC Qualified: N; VDC_V: 75V; AEC Category: Q200; SizeAreaWB_mm2: 4.68
R8 = CMP-0022008-4: RES, 110 k, 1%, 0.1 W, AEC-Q200 Grade 0, 0603; Manufacturer: Vishay-Dale; Power_W: 100mW; TempCo: 100 ppm/C; Value: 110k; EIA_Code: E96; SizeX_mm: 1.6; SizeY_mm: 0.8; SizeZ_mm: 1; Value2: 0.1W; SizeArea_mm2: 1.28; AEC Qualified: Y; VDC_V: 75V; AEC Category: Q200; AEC Grade: 0
R9 R10 = CMP-0022707-2: RES, 49.9, 1%, 0.1 W, AEC-Q200 Grade 0, 0603; Manufacturer: Panasonic; Power_W: 100mW; TempCo: 100 ppm/C; Value_Code: 49R9; Value: 49.9; EIA_Code: E96; SizeX_mm: 1.6; SizeY_mm: 0.8; SizeZ_mm: 1; Value2: 0.1W; SizeArea_mm2: 1.28; AEC Qualified: Y; AEC Category: Q200; AEC Grade: 0; U/M: EA
R11 = CMP-0022707-2: RES, 49.9, 1%, 0.1 W, AEC-Q200 Grade 0, 0603; Manufacturer: Panasonic; Power_W: 100mW; TempCo: 100 ppm/C; SizeZ_mm: 1; AEC Qualified: Y; AEC Grade: 0; Value_Code: 49R9; Value: 49.9; EIA_Code: E96; SizeX_mm: 1.6; Value2: 0.1W; SizeArea_mm2: 1.28; AEC Category: Q200; SizeY_mm: 0.8; U/M: EA
R13 = CMP-0023155-5: RES, 4.99 k, 1%, 0.1 W, 0603; Manufacturer: Yageo; Power_W: 100mW; TempCo: 100 ppm/C; Value_Code: 4k99; Value: 4.99k; EIA_Code: E96; SizeX_mm: 1.6; SizeY_mm: 0.8; SizeZ_mm: 1; Value2: 0.1W; SizeArea_mm2: 1.28; AEC Qualified: N; VDC_V: 75V; AEC Category: Q200; SizeAreaWB_mm2: 4.68
R14 = CMP-0023311-5: RES, 8.87 k, 1%, 0.1 W, 0603; Manufacturer: Yageo; Power_W: 100mW; TempCo: 100 ppm/C; Value_Code: 8k87; Value: 8.87k; EIA_Code: E96; SizeX_mm: 1.6; SizeY_mm: 0.8; SizeZ_mm: 1; Value2: 0.1W; SizeArea_mm2: 1.28; AEC Qualified: N; VDC_V: 75V; AEC Category: Q200; SizeAreaWB_mm2: 4.68
R15 = CMP-0023335-5: RES, 9.53 k, 1%, 0.1 W, 0603; Manufacturer: Yageo; Power_W: 100mW; TempCo: 100 ppm/C; Value_Code: 9k53; Value: 9.53k; EIA_Code: E96; SizeX_mm: 1.6; SizeY_mm: 0.8; SizeZ_mm: 1; Value2: 0.1W; SizeArea_mm2: 1.28; AEC Qualified: N; VDC_V: 75V; AEC Category: Q200; SizeAreaWB_mm2: 4.68
R16 = CMP-0022994-5: RES, 2.67 k, 1%, 0.1 W, 0603; Manufacturer: Yageo; Power_W: 100mW; TempCo: 100 ppm/C; Value_Code: 2k67; Value: 2.67k; EIA_Code: E96; SizeX_mm: 1.6; SizeY_mm: 0.8; SizeZ_mm: 1; Value2: 0.1W; SizeArea_mm2: 1.28; AEC Qualified: N; VDC_V: 75V; AEC Category: Q200; SizeAreaWB_mm2: 4.68
R17 = CMP-0023066-5: RES, 38.3 k, 1%, 0.1 W, 0603; Manufacturer: Yageo; Power_W: 100mW; TempCo: 100 ppm/C; Value_Code: 38k3; Value: 38.3k; EIA_Code: E96; SizeX_mm: 1.6; SizeY_mm: 0.8; SizeZ_mm: 1; Value2: 0.1W; SizeArea_mm2: 1.28; AEC Qualified: N; VDC_V: 75V; AEC Category: Q200; SizeAreaWB_mm2: 4.68
R18 = CMP-0023205-5: RES, 5.90 k, 1%, 0.1 W, 0603; Manufacturer: Yageo; Power_W: 100mW; TempCo: 100 ppm/C; Value_Code: 5k90; Value: 5.90k; EIA_Code: E96; Res_ohm: 5.9k; SizeX_mm: 1.6; SizeY_mm: 0.8; SizeZ_mm: 1; Value2: 0.1W; SizeArea_mm2: 1.28; AEC Qualified: N; VDC_V: 75V; AEC Category: Q200; SizeAreaWB_mm2: 4.68
R20 = CMP-0080492-1: RES, 49.9, 1%, 0.1 W, 0603; Manufacturer: TT Electronics/IRC; Power_W: 100mW; TempCo: 100 ppm/C; SizeAreaWB_mm2: 4.68; Value_Code: 49R9; Value: 49.9; EIA_Code: E96; SizeX_mm: 1.6; SizeY_mm: 0.8; SizeZ_mm: 1; Value2: 0.1W; SizeArea_mm2: 1.28; AEC Qualified: N; AEC Category: Q200
R22 = CMP-0023277-5: RES, 7.15 k, 1%, 0.1 W, 0603; Manufacturer: Yageo; Power_W: 100mW; TempCo: 100 ppm/C; Value_Code: 7k15; Value: 7.15k; EIA_Code: E96; SizeX_mm: 1.6; SizeY_mm: 0.8; SizeZ_mm: 1; Value2: 0.1W; SizeArea_mm2: 1.28; AEC Qualified: N; VDC_V: 75V; AEC Category: Q200; SizeAreaWB_mm2: 4.68
R23 = CMP-0025899-5: RES, 1.0 k, 5%, 0.1 W, 0603; Manufacturer: Yageo; Power_W: 100mW; TempCo: 100 ppm/C; Value_Code: 1k00; Value: 1.0k; EIA_Code: E24; Res_ohm: 1k; SizeX_mm: 1.6; SizeY_mm: 0.8; SizeZ_mm: 1; Value2: 0.1W; SizeArea_mm2: 1.28; AEC Qualified: N; VDC_V: 75V; AEC Category: Q200; SizeAreaWB_mm2: 4.68
TP1 TP3 = CMP-0055137-2: Test Point, Miniature, Red, TH; Manufacturer: Keystone Electronics; Green_REACh: Passed; CT: TRUE; ContactFinish: Silver; CNHeader: FALSE; Green_Lifecycle: Active
TP2 TP4 = CMP-0055138-2: Test Point, Miniature, Black, TH; Manufacturer: Keystone Electronics; ContactFinish: Silver; CNHeader: FALSE; Green_Lifecycle: Active; Green_REACh: Passed; CT: TRUE
U1 = CMP-0120283-1: 80V Synchronous Buck Controller with Constant Current Constant Voltage Regulation; Manufacturer: Texas Instruments; SizeZ_mm: 1mm; AEC Qualified: Yes; AEC Grade: Grade 1; Min Supply Voltage: 5V; Nominal Supply Current: 125uA; Number Of Outputs: 1; Output Type: AdjustableProgrammable; Output Voltage: 0.8-80V; Standoff Height: 0mm; Switching Frequency: 100-2200kHz; TaMax_C: +125°C; TaMin_C: -40°C; TJmax_C: +150°C

## Sheet SR043A_Hardware.SchDoc: LM5190QEVM-400 Hardware
size 431 x 279 mm; Date: Not shown in title block; ApprovedBy: Not shown in title block; CheckedBy: Not shown in title block; Author: Not shown in title block; CompanyName: Not shown in title block; DrawnBy: K Nielson; Engineer: Not shown in title block; Organization: Not shown in title block; Address1: Not shown in title block; Address2: Not shown in title block; Address3: Not shown in title block; Address4: Not shown in title block; DocumentNumber: 2; Revision: Use project parameter SCH_Rev; SheetNumber: 2; SheetTotal: 2; PageSetup: Record=PageOptions¦CenterHorizontal=True¦CenterVertical=True¦PrintScale=1.00¦XCorrection=1.00¦YCorrection=1.00¦PrintKind=0¦BorderSize=5000000¦LeftOffset=0¦BottomOffset=0¦Orientation=2¦PaperLength=1000¦PaperWidth=1000¦Scale=100¦PaperSource=15¦PrintQuality=600¦MediaType=1¦DitherType=10¦PaperKind=Letter¦PrintScaleMode=1
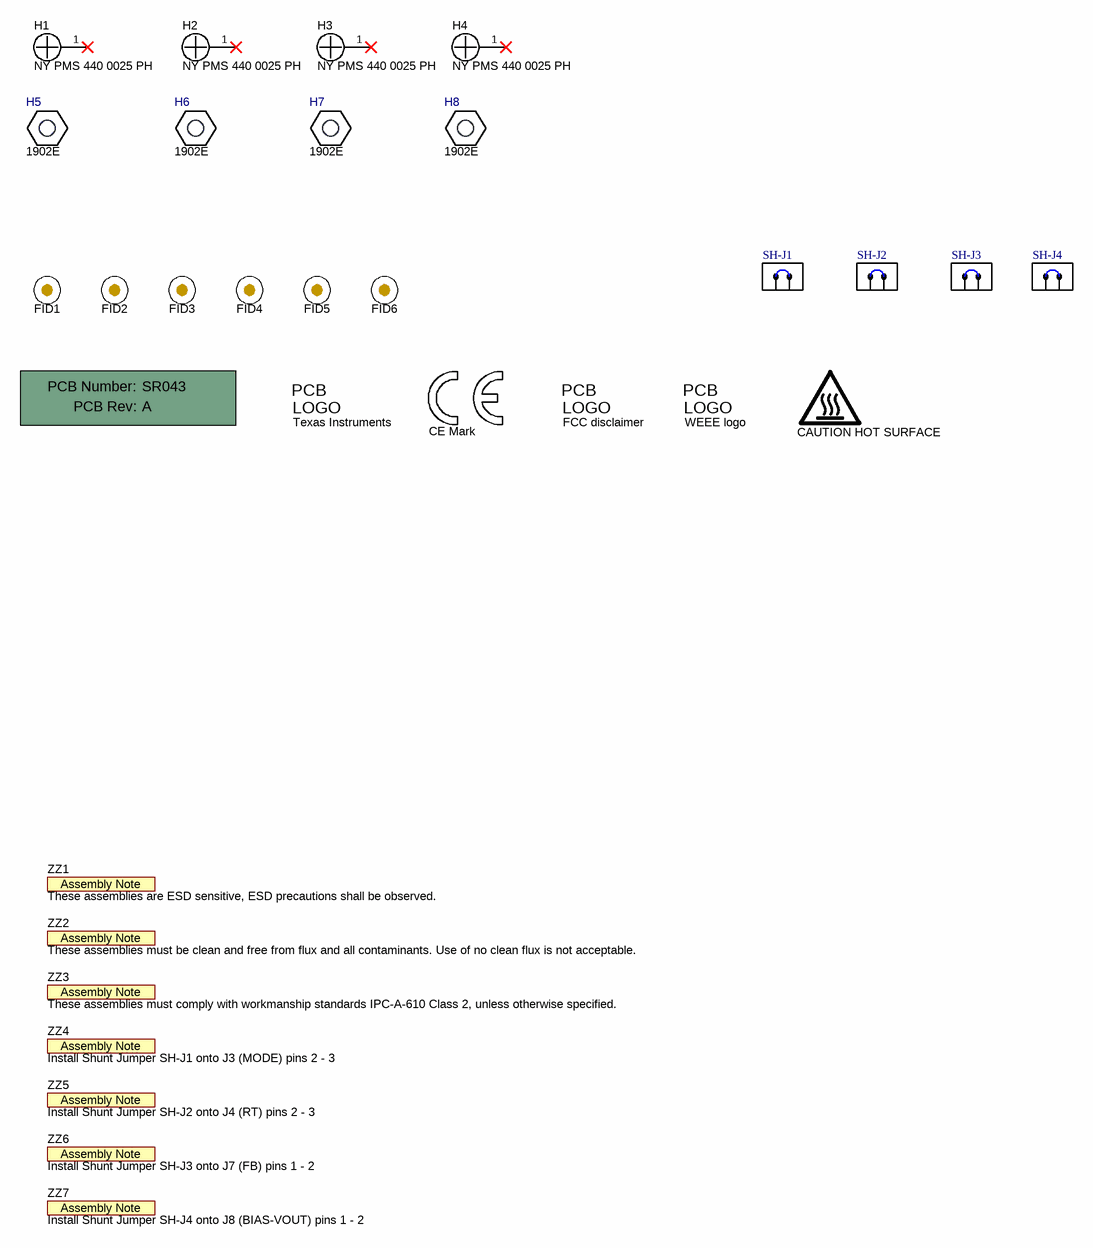
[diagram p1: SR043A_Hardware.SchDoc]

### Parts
!PCB1  Printed Circuit Board  (value not drawn)  (mechanical)
FID1  Fiducial  [Fiducial10-20]  (value not drawn)
FID2  Fiducial  [Fiducial10-20]  (value not drawn)
FID3  Fiducial  [Fiducial10-20]  (value not drawn)
FID4  Fiducial  [Fiducial10-20]  (value not drawn)
FID5  Fiducial  [Fiducial10-20]  (value not drawn)
FID6  Fiducial  [Fiducial10-20]  (value not drawn)
H1  NY PMS 440 0025 PH  [NY PMS 440 0025 PH]
H2  NY PMS 440 0025 PH  [NY PMS 440 0025 PH]
H3  NY PMS 440 0025 PH  [NY PMS 440 0025 PH]
H4  NY PMS 440 0025 PH  [NY PMS 440 0025 PH]
H5  1902E  [Keystone_1902E]
H6  1902E  [Keystone_1902E]
H7  1902E  [Keystone_1902E]
H8  1902E  [Keystone_1902E]
Logo1  CAUTION HOT SURFACE  [IEC_HotSurface_Small]  (no BOM)
Logo2  CE Mark  [CE_Mark_5mm]  (no BOM)
Logo3  Texas Instruments  [TI_Stacked_Overlay_Small]  (no BOM)
Logo4  FCC disclaimer  [FCC_disclaimer]  (no BOM)
Logo5  WEEE logo  [WEEE_Minimum]  (no BOM)
SH-J1  M7582-05  [Harwin_M7582-05]  (value not drawn)
SH-J2  M7582-05  [Harwin_M7582-05]  (value not drawn)
SH-J3  M7582-05  [Harwin_M7582-05]  (value not drawn)
SH-J4  M7582-05  [Harwin_M7582-05]  (value not drawn)
ZZ1  These assemblies are ESD sensitive, ESD precautions shall be observed.  [AssemblyNote]  (no BOM)
ZZ2  These assemblies must be clean and free from flux and all contaminants. Use of no clean flux is not acceptable.  [AssemblyNote]  (no BOM)
ZZ3  These assemblies must comply with workmanship standards IPC-A-610 Class 2, unless otherwise specified.  [AssemblyNote]  (no BOM)
ZZ4  Install Shunt Jumper SH-J1 onto J3 (MODE) pins 2 - 3  [AssemblyNote]  (no BOM)
ZZ5  Install Shunt Jumper SH-J2 onto J4 (RT) pins 2 - 3  [AssemblyNote]  (no BOM)
ZZ6  Install Shunt Jumper SH-J3 onto J7 (FB) pins 1 - 2  [AssemblyNote]  (no BOM)
ZZ7  Install Shunt Jumper SH-J4 onto J8 (BIAS-VOUT) pins 1 - 2  [AssemblyNote]  (no BOM)

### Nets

Not connected (* = marked no-connect by the designer): H1 1*; H2 1*; H3 1*; H4 1*

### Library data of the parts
!PCB1 = CMP-0003618-2: Manufacturer: Any; PartNumber: SR043
FID1-FID6 = CMP-0077181-1: Fiducial mark.  There is nothing to buy or mount.
H1-H4 = CMP-0003617-1: Machine Screw, Round, #4-40 x 1/4, Nylon, Philips panhead; Manufacturer: B&F Fastener Supply; CompType: Hardware
H5-H8 = CMP-0003611-1: Standoff, Hex, 1"L #4-40 Nylon; Manufacturer: Keystone; CompType: Hardware
Logo1 = CMP-0074837-2: IEC 61010-1 Hot Surface Warning; Manufacturer: Texas Instruments; CompType: IC; AEC Category: Q200; SymbolCreator: a0412235
Logo2 = CMP-0074844-1: SymbolCreator: a0412235
Logo3 = CMP-0074838-1: Texas Instrument Corporate Signature; SymbolCreator: a0412235; Lib Reference: TI_Logo; Library Reference: Logo
Logo4 = CMP-0074847-1: FCC_disclaimer; Library Reference: Logo
Logo5 = CMP-0074769-3: Manufacturer: Texas Instruments; CompType: IC; AEC Category: Q200
SH-J1-SH-J4 = CMP-0078738-1: Single Operation 2.54mm Pitch Open Top Jumper Socket; Manufacturer: Harwin
ZZ1 = CMP-0077236-1
ZZ2 = CMP-0077237-1
ZZ3 = CMP-0077238-1
ZZ4-ZZ7 = CMP-0077238-1: These assemblies must comply with workmanship standards IPC-A-610 Class 2, unless otherwise specified.

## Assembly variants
001: not fitted C2 C3 C4 C5 C6 C9 C10 C11 C12 C31 C36 C45 FB1 FID1 FID2 FID3 FID4 FID5 FID6 J2 L1 L2 L2A R8 R9 R10 R14 R16 R17 R19 R20 R22 R23 TP1 TP2 TP3 TP4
